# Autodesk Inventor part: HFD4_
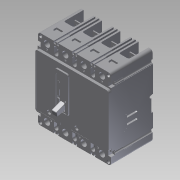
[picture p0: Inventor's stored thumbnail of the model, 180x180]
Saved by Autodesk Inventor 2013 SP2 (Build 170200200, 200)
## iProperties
Created: 2014-08
Part Number: HFD4_
Material: Generic
Document SubType Name: Modeling
Designer: DM/JS
Density: 1 g/cm^3
Description: TYPE HFD THERMAL MAGNETIC CIRCUIT BREAKERS FOUR POLE, SERIES C
Translation Standard: STEP AP214IS
FileName: Y:\ECO-062745\WIP\New\FD4_.stp
PreProcessor: Autodesk Inventor 2012
PostProcessor: Build: 219, Release: 2012 SP2 - Date: Fri 04/27/2012
Sent Units: inch
Uncertainty: 0.00039370078740199997
MXEDIT: false
MXINVTNRV: INV Versioned Component|HFD4_|003.0
Author: DM/JS
Revision Number: 003
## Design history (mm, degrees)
node "HFD4_"
node "L1"
node "L2"
node "L3"
node "L4"
node "T1"
node "T2"
node "T3"
node "T4"
body "Solid1"
node "Base1"
